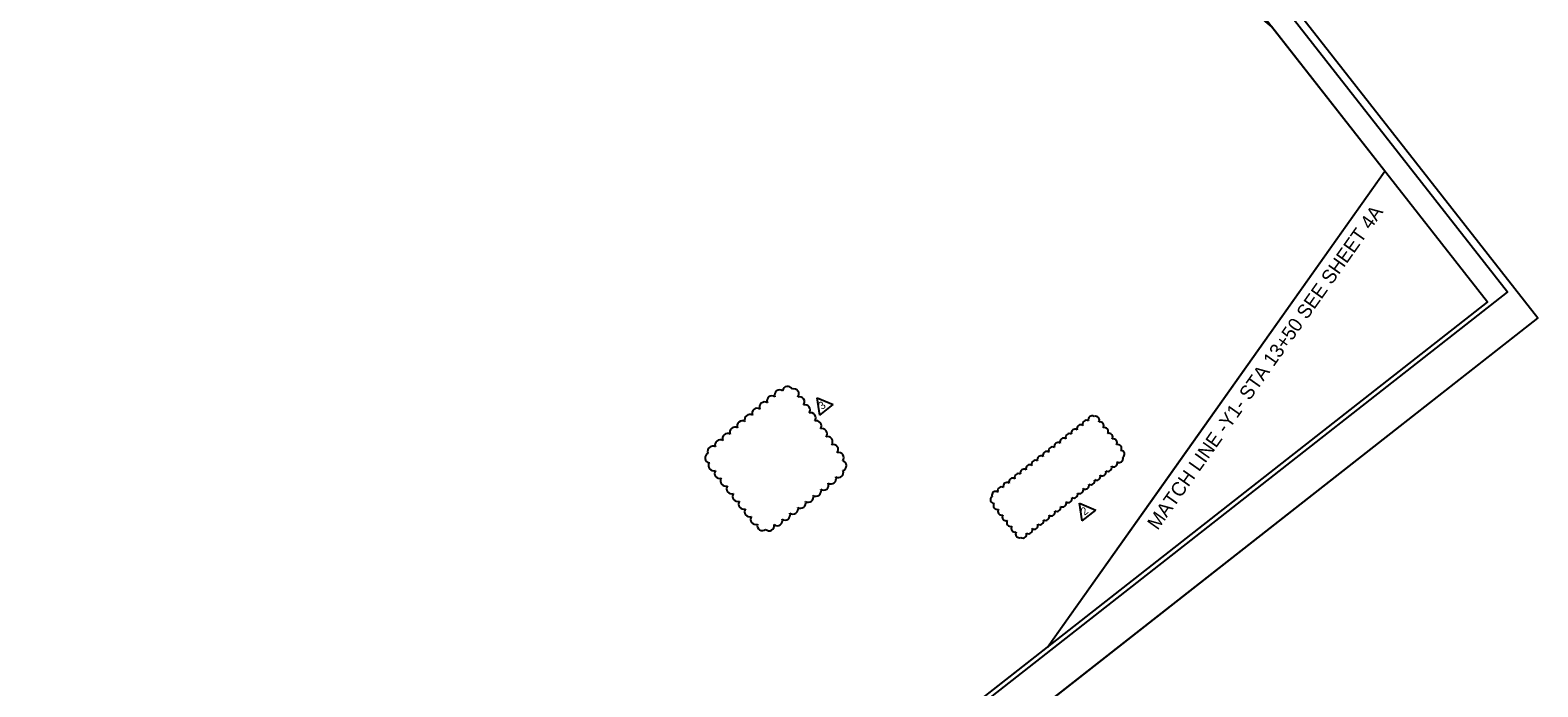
# Model space of a CAD drawing. Extents: x 2174973 to 2176977, y 76106 to 78055.
# Drawn here: x 2176114 to 2176977, y 76934 to 77310 of the extents above; entities that cross this region are included whole.
import ezdxf

# ---------------------------------------------------------------- set-up
doc = ezdxf.new("R2010")
doc.units = 0
for name, color, linetype in [('CTL Primary Horizontal and Vertical CELL', 7, 'Continuous'), ('CTL Primary Horizontal CELL', 7, 'Continuous'), ('CTL Primary Horizontal Cogo Elevation', 7, 'Continuous'), ('CTL Primary Horizontal Cogo Number', 7, 'Continuous'), ('Exist Other Culture Sign Cogo Point CELL', 7, 'Continuous'), ('Exist Structure Minor Pipes RCP 18 Inch', 7, 'Continuous'), ('Exist Utilities Other Traffic Signal Box CELL', 7, 'Continuous')]:
    doc.layers.add(name, color=color, linetype=linetype)

msp = doc.modelspace()

# ---------------------------------------------------------------- linework, layer by layer
at = {"layer": 'CTL Primary Horizontal and Vertical CELL'}
msp.add_lwpolyline([(2175306.56, 76817.11), (2175665.08, 76359.73), (2175813.77, 76476.34), (2175916.67, 76345.14), (2176696.59, 76956.56), (2176763.63, 77051.2), (2176889.59, 77229), (2176824.75, 77311.73), (2176559.15, 77534.36), (2176539.41, 77550.91), (2176367.65, 77694.89), (2176358.97, 77688.08), (2176301.94, 77760.83), (2176250.28, 77720.34), (2176235.78, 77738.83), (2176166.38, 77827.37), (2176143.21, 77856.93), (2175957.17, 77711.1), (2175525.72, 77372.91), (2175451.32, 77314.59), (2175120.11, 77054.97)], close=True, dxfattribs=at)
at = {"layer": 'CTL Primary Horizontal CELL'}
msp.add_lwpolyline([(2176308.92, 77990.06), (2174997.34, 76961.97), (2175648.24, 76131.58), (2176959.83, 77159.66)], close=True, dxfattribs=at)
at = {"layer": 'CTL Primary Horizontal Cogo Elevation'}
msp.add_line((2175651.86, 76105.89), (2176977.22, 77144.77), dxfattribs=at)
at = {"layer": 'CTL Primary Horizontal Cogo Number'}
msp.add_lwpolyline([(2176298.62, 78010.5), (2174973.26, 76971.62), (2175651.86, 76105.89), (2176977.22, 77144.77)], close=True, dxfattribs=at)
at = {"layer": 'Exist Other Culture Sign Cogo Point CELL'}
msp.add_lwpolyline([(2176300.66, 77980.34), (2175120.11, 77054.97), (2175767.87, 76228.59), (2176948.42, 77153.96)], close=True, dxfattribs=at)
at = {"layer": 'Exist Structure Minor Pipes RCP 18 Inch'}
for p, q in [((2176564.63, 77099.31), (2176573.97, 77095.45)), ((2176566.15, 77089.32), (2176564.63, 77099.31)), ((2176566.15, 77089.32), (2176573.97, 77095.45)), ((2176714.87, 77038.86), (2176724.21, 77034.99)), ((2176716.4, 77028.87), (2176714.87, 77038.86)), ((2176716.4, 77028.87), (2176724.21, 77034.99))]:
    msp.add_line(p, q, dxfattribs=at)
for centre, radius, start, end in [((2176538.92, 77097.47), 2.92, 56.40905, 201.40905), ((2176543.29, 77100.9), 2.92, 54.93962, 199.93962), ((2176547.86, 77102.89), 2.92, 27.24132, 172.24132), ((2176551.36, 77101.45), 2.92, 322.95607, 107.95607), ((2176554.58, 77096.91), 2.92, 322.78454, 107.78454), ((2176526.09, 77086.78), 2.92, 57.92086, 202.92086), ((2176530.34, 77090.38), 2.92, 57.60182, 202.60182), ((2176534.62, 77093.94), 2.92, 57.14146, 202.14146), ((2176557.8, 77092.36), 2.92, 322.72115, 107.72115), ((2176561.01, 77087.8), 2.92, 322.6851, 107.6851), ((2176517.62, 77079.54), 2.92, 58.00914, 203.00914), ((2176521.85, 77083.16), 2.92, 58.00914, 203.00914), ((2176564.22, 77083.25), 2.92, 322.66336, 107.66336), ((2176567.43, 77078.69), 2.92, 322.67688, 107.67688), ((2176712.34, 77079.16), 2.16, 55.59105, 200.59105), ((2176715.59, 77081.71), 2.16, 55.59105, 200.59105), ((2176718.84, 77084.25), 2.16, 55.59105, 200.59105), ((2176722.08, 77086.8), 2.16, 55.59105, 200.59105), ((2176724.07, 77086.56), 2.16, 325.59105, 110.59105), ((2176726.61, 77083.31), 2.16, 325.59105, 110.59105), ((2176729.16, 77080.07), 2.16, 325.59105, 110.59105), ((2176509.14, 77072.3), 2.92, 58.00914, 203.00914), ((2176513.38, 77075.92), 2.92, 58.00914, 203.00914), ((2176570.64, 77074.14), 2.92, 322.70839, 107.70839), ((2176573.86, 77069.58), 2.92, 322.76049, 107.76049), ((2176702.6, 77071.53), 2.16, 55.59105, 200.59105), ((2176705.85, 77074.07), 2.16, 55.59105, 200.59105), ((2176709.09, 77076.62), 2.16, 55.59105, 200.59105), ((2176731.7, 77076.82), 2.16, 325.59105, 110.59105), ((2176734.25, 77073.57), 2.16, 325.59105, 110.59105), ((2176736.79, 77070.32), 2.16, 325.59105, 110.59105), ((2176503.48, 77064.9), 2.92, 115.66765, 260.66765), ((2176504.9, 77068.68), 2.92, 58.00914, 203.00914), ((2176577.08, 77065.03), 2.92, 322.87617, 107.87617), ((2176689.61, 77061.35), 2.16, 55.59105, 200.59105), ((2176692.86, 77063.89), 2.16, 55.59105, 200.59105), ((2176696.1, 77066.44), 2.16, 55.59105, 200.59105), ((2176699.35, 77068.98), 2.16, 55.59105, 200.59105), ((2176737.67, 77064.37), 2.16, 235.59105, 20.59105), ((2176738.51, 77066.94), 2.16, 303.25906, 88.25906), ((2176505.42, 77060.37), 2.92, 145.59105, 290.59105), ((2176508.86, 77055.98), 2.92, 145.59105, 290.59105), ((2176576.82, 77056.48), 2.92, 239.5794, 24.5794), ((2176578.56, 77060.47), 2.92, 288.12443, 73.12443), ((2176679.87, 77053.71), 2.16, 55.59105, 200.59105), ((2176683.11, 77056.26), 2.16, 55.59105, 200.59105), ((2176686.36, 77058.8), 2.16, 55.59105, 200.59105), ((2176724.68, 77054.19), 2.16, 235.59105, 20.59105), ((2176727.93, 77056.73), 2.16, 235.59105, 20.59105), ((2176731.18, 77059.28), 2.16, 235.59105, 20.59105), ((2176734.43, 77061.83), 2.16, 235.59105, 20.59105), ((2176512.29, 77051.6), 2.92, 145.59105, 290.59105), ((2176515.73, 77047.21), 2.92, 145.59105, 290.59105), ((2176564.01, 77045.82), 2.92, 235.99746, 20.99746), ((2176568.35, 77049.31), 2.92, 236.54765, 21.54765), ((2176572.64, 77052.85), 2.92, 237.46846, 22.46846), ((2176670.13, 77046.07), 2.16, 55.59105, 200.59105), ((2176673.37, 77048.62), 2.16, 55.59105, 200.59105), ((2176676.62, 77051.16), 2.16, 55.59105, 200.59105), ((2176714.94, 77046.55), 2.16, 235.59105, 20.59105), ((2176718.19, 77049.1), 2.16, 235.59105, 20.59105), ((2176721.44, 77051.64), 2.16, 235.59105, 20.59105), ((2176519.17, 77042.82), 2.92, 145.59105, 290.59105), ((2176522.61, 77038.44), 2.92, 145.59105, 290.59105), ((2176555.25, 77038.95), 2.92, 235.25945, 20.25945), ((2176559.64, 77042.37), 2.92, 235.61877, 20.61877), ((2176666.04, 77040.96), 2.16, 123.25906, 268.25906), ((2176666.88, 77043.53), 2.16, 55.59105, 200.59105), ((2176667.76, 77037.58), 2.16, 145.59105, 290.59105), ((2176705.2, 77038.92), 2.16, 235.59105, 20.59105), ((2176708.45, 77041.46), 2.16, 235.59105, 20.59105), ((2176711.69, 77044.01), 2.16, 235.59105, 20.59105), ((2176526.05, 77034.05), 2.92, 145.59105, 290.59105), ((2176529.5, 77029.68), 2.92, 146.00029, 291.00029), ((2176541.88, 77028.98), 2.92, 232.53517, 17.53517), ((2176546.38, 77032.22), 2.92, 233.99439, 18.99439), ((2176550.83, 77035.56), 2.92, 234.7639, 19.7639), ((2176670.3, 77034.33), 2.16, 145.59105, 290.59105), ((2176672.85, 77031.08), 2.16, 145.59105, 290.59105), ((2176675.39, 77027.83), 2.16, 145.59105, 290.59105), ((2176692.21, 77028.74), 2.16, 235.59105, 20.59105), ((2176695.46, 77031.28), 2.16, 235.59105, 20.59105), ((2176698.7, 77033.83), 2.16, 235.59105, 20.59105), ((2176701.95, 77036.37), 2.16, 235.59105, 20.59105), ((2176533.37, 77026.19), 2.92, 164.80768, 309.80768), ((2176537.24, 77026.07), 2.92, 226.6807, 11.6807), ((2176677.94, 77024.59), 2.16, 145.59105, 290.59105), ((2176680.48, 77021.34), 2.16, 145.59105, 290.59105), ((2176682.47, 77021.1), 2.16, 235.59105, 20.59105), ((2176685.72, 77023.64), 2.16, 235.59105, 20.59105), ((2176688.96, 77026.19), 2.16, 235.59105, 20.59105)]:
    msp.add_arc(centre, radius, start, end, dxfattribs=at)
at = {"layer": 'Exist Utilities Other Traffic Signal Box CELL'}
msp.add_line((2176696.59, 76956.56), (2176889.59, 77229), dxfattribs=at)

# ---------------------------------------------------------------- texts
at = {"layer": 'Exist Structure Minor Pipes RCP 18 Inch'}
for s, p in [('3', (2176567.49, 77092.13)), ('2', (2176717.74, 77031.68))]:
    msp.add_text(s, height=4.5, rotation=38.09105, dxfattribs=at).set_placement(p)
at = {"layer": 'Exist Utilities Other Traffic Signal Box CELL'}
msp.add_text('MATCH LINE -Y1- STA 13+50 SEE SHEET 4A', height=8, rotation=54.68504, dxfattribs=at).set_placement((2176759.61, 77023.07))

doc.saveas('drawing.dxf')
